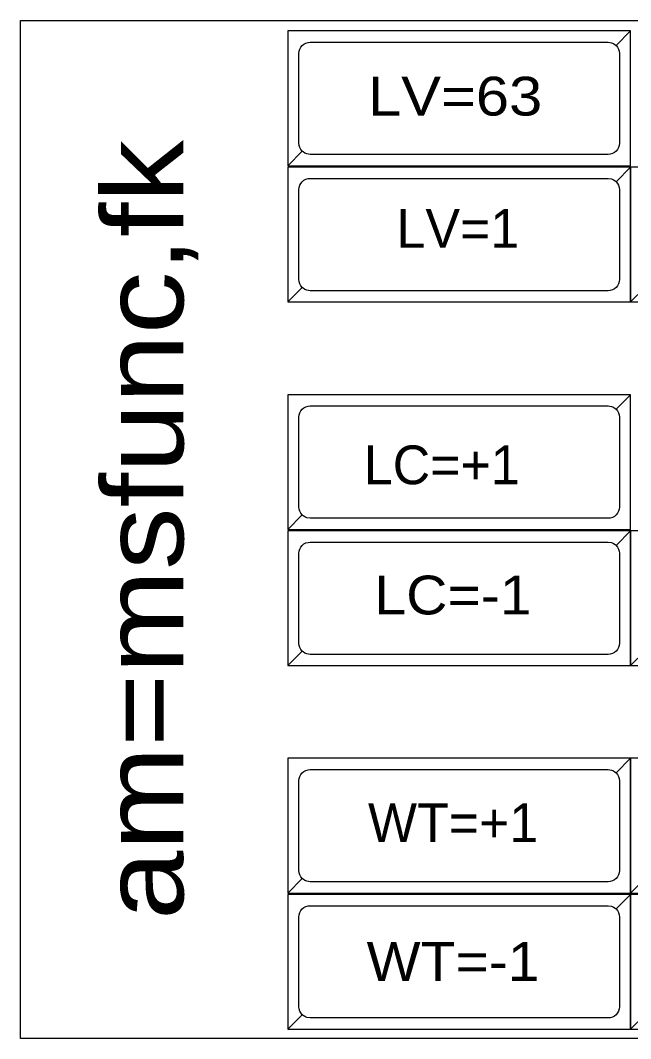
# Model space of a CAD drawing. Extents: x 16898 to 16911.6, y 15837.8 to 15842.
# Drawn here: x 16897.996 to 16899.217, y 15839.972 to 15842.012 of the extents above; entities that cross this region are included whole.
import ezdxf
from ezdxf.enums import TextEntityAlignment as Align

# ---------------------------------------------------------------- set-up
doc = ezdxf.new("R2010")
doc.units = 0
doc.header["$LTSCALE"] = 0.018
for name, color, linetype, lineweight in [('1', 7, 'Continuous', 25), ('2', 7, 'Continuous', 13), ('5', 7, 'Continuous', 13)]:
    doc.layers.add(name, color=color, linetype=linetype, lineweight=lineweight)

msp = doc.modelspace()

# ---------------------------------------------------------------- linework, layer by layer
at = {"layer": '1'}
for points in [[(16897.9955, 15839.9723), (16897.9955, 15842.0124), (16911.4764, 15842.0124), (16911.5674, 15841.9251), (16911.5674, 15840.0599), (16911.4764, 15839.9723)], [(16898.5307, 15841.7212), (16899.2171, 15841.7212), (16899.2171, 15841.9912), (16898.5307, 15841.9912)], [(16898.5307, 15841.7212), (16899.2171, 15841.7212), (16899.2171, 15841.9912), (16899.188, 15841.9621), (16899.1908, 15841.9587), (16899.1929, 15841.9548), (16899.1941, 15841.9506), (16899.1946, 15841.9462), (16899.1946, 15841.7662), (16899.1941, 15841.7618), (16899.1929, 15841.7576), (16899.1908, 15841.7537), (16899.188, 15841.7503), (16899.188, 15841.7503), (16899.1846, 15841.7475), (16899.1807, 15841.7454), (16899.1765, 15841.7441), (16899.1721, 15841.7437), (16898.5757, 15841.7437), (16898.5691, 15841.7447), (16898.5651, 15841.7464), (16898.5614, 15841.7488), (16898.5598, 15841.7503)], [(16899.2171, 15841.9912), (16898.5307, 15841.9912), (16898.5307, 15841.7212), (16898.5598, 15841.7503), (16898.557, 15841.7537), (16898.5549, 15841.7576), (16898.5536, 15841.7618), (16898.5532, 15841.7662), (16898.5532, 15841.9462), (16898.5536, 15841.9506), (16898.5549, 15841.9548), (16898.557, 15841.9587), (16898.5598, 15841.9621), (16898.5598, 15841.9621), (16898.5632, 15841.9649), (16898.5671, 15841.967), (16898.5713, 15841.9682), (16898.5757, 15841.9687), (16899.1721, 15841.9687), (16899.1787, 15841.9677), (16899.1827, 15841.966), (16899.1864, 15841.9636), (16899.188, 15841.9621)], [(16898.5307, 15841.4483), (16899.2171, 15841.4483), (16899.2171, 15841.7183), (16898.5307, 15841.7183)], [(16898.5307, 15841.4483), (16899.2171, 15841.4483), (16899.2171, 15841.7183), (16899.188, 15841.6892), (16899.1908, 15841.6858), (16899.1929, 15841.6819), (16899.1941, 15841.6777), (16899.1946, 15841.6733), (16899.1946, 15841.4933), (16899.1941, 15841.4889), (16899.1929, 15841.4847), (16899.1908, 15841.4808), (16899.188, 15841.4774), (16899.188, 15841.4774), (16899.1846, 15841.4746), (16899.1807, 15841.4725), (16899.1765, 15841.4712), (16899.1721, 15841.4708), (16898.5757, 15841.4708), (16898.5691, 15841.4718), (16898.5651, 15841.4735), (16898.5614, 15841.4759), (16898.5598, 15841.4774)], [(16899.2171, 15841.7183), (16898.5307, 15841.7183), (16898.5307, 15841.4483), (16898.5598, 15841.4774), (16898.557, 15841.4808), (16898.5549, 15841.4847), (16898.5536, 15841.4889), (16898.5532, 15841.4933), (16898.5532, 15841.6733), (16898.5536, 15841.6777), (16898.5549, 15841.6819), (16898.557, 15841.6858), (16898.5598, 15841.6892), (16898.5598, 15841.6892), (16898.5632, 15841.692), (16898.5671, 15841.6941), (16898.5713, 15841.6953), (16898.5757, 15841.6958), (16899.1721, 15841.6958), (16899.1787, 15841.6948), (16899.1827, 15841.6931), (16899.1864, 15841.6907), (16899.188, 15841.6892)], [(16899.2171, 15841.4483), (16899.9035, 15841.4483), (16899.9035, 15841.7183), (16899.2171, 15841.7183)], [(16899.2171, 15841.4483), (16899.9035, 15841.4483), (16899.9035, 15841.7183), (16899.8744, 15841.6892), (16899.8772, 15841.6858), (16899.8793, 15841.6819), (16899.8805, 15841.6777), (16899.881, 15841.6733), (16899.881, 15841.4933), (16899.8805, 15841.4889), (16899.8793, 15841.4847), (16899.8772, 15841.4808), (16899.8744, 15841.4774), (16899.8744, 15841.4774), (16899.871, 15841.4746), (16899.8671, 15841.4725), (16899.8629, 15841.4712), (16899.8585, 15841.4708), (16899.2621, 15841.4708), (16899.2555, 15841.4718), (16899.2515, 15841.4735), (16899.2478, 15841.4759), (16899.2462, 15841.4774)], [(16899.9035, 15841.7183), (16899.2171, 15841.7183), (16899.2171, 15841.4483), (16899.2462, 15841.4774), (16899.2434, 15841.4808), (16899.2413, 15841.4847), (16899.24, 15841.4889), (16899.2396, 15841.4933), (16899.2396, 15841.6733), (16899.24, 15841.6777), (16899.2413, 15841.6819), (16899.2434, 15841.6858), (16899.2462, 15841.6892), (16899.2462, 15841.6892), (16899.2496, 15841.692), (16899.2535, 15841.6941), (16899.2577, 15841.6953), (16899.2621, 15841.6958), (16899.8585, 15841.6958), (16899.8651, 15841.6948), (16899.8691, 15841.6931), (16899.8728, 15841.6907), (16899.8744, 15841.6892)], [(16898.5307, 15840.9924), (16899.2171, 15840.9924), (16899.2171, 15841.2624), (16898.5307, 15841.2624)], [(16898.5307, 15840.9924), (16899.2171, 15840.9924), (16899.2171, 15841.2624), (16899.188, 15841.2333), (16899.1908, 15841.2299), (16899.1929, 15841.226), (16899.1941, 15841.2218), (16899.1946, 15841.2174), (16899.1946, 15841.0374), (16899.1941, 15841.033), (16899.1929, 15841.0288), (16899.1908, 15841.0249), (16899.188, 15841.0215), (16899.188, 15841.0215), (16899.1846, 15841.0187), (16899.1807, 15841.0166), (16899.1765, 15841.0153), (16899.1721, 15841.0149), (16898.5757, 15841.0149), (16898.5691, 15841.0159), (16898.5651, 15841.0176), (16898.5614, 15841.02), (16898.5598, 15841.0215)], [(16899.2171, 15841.2624), (16898.5307, 15841.2624), (16898.5307, 15840.9924), (16898.5598, 15841.0215), (16898.557, 15841.0249), (16898.5549, 15841.0288), (16898.5536, 15841.033), (16898.5532, 15841.0374), (16898.5532, 15841.2174), (16898.5536, 15841.2218), (16898.5549, 15841.226), (16898.557, 15841.2299), (16898.5598, 15841.2333), (16898.5598, 15841.2333), (16898.5632, 15841.2361), (16898.5671, 15841.2382), (16898.5713, 15841.2394), (16898.5757, 15841.2399), (16899.1721, 15841.2399), (16899.1787, 15841.2389), (16899.1827, 15841.2372), (16899.1864, 15841.2348), (16899.188, 15841.2333)], [(16898.5307, 15840.7196), (16899.2171, 15840.7196), (16899.2171, 15840.9896), (16898.5307, 15840.9896)], [(16898.5307, 15840.7196), (16899.2171, 15840.7196), (16899.2171, 15840.9896), (16899.188, 15840.9605), (16899.1908, 15840.9571), (16899.1929, 15840.9532), (16899.1941, 15840.949), (16899.1946, 15840.9446), (16899.1946, 15840.7646), (16899.1941, 15840.7602), (16899.1929, 15840.756), (16899.1908, 15840.7521), (16899.188, 15840.7487), (16899.188, 15840.7487), (16899.1846, 15840.7459), (16899.1807, 15840.7438), (16899.1765, 15840.7425), (16899.1721, 15840.7421), (16898.5757, 15840.7421), (16898.5691, 15840.7431), (16898.5651, 15840.7448), (16898.5614, 15840.7472), (16898.5598, 15840.7487)], [(16899.2171, 15840.9896), (16898.5307, 15840.9896), (16898.5307, 15840.7196), (16898.5598, 15840.7487), (16898.557, 15840.7521), (16898.5549, 15840.756), (16898.5536, 15840.7602), (16898.5532, 15840.7646), (16898.5532, 15840.9446), (16898.5536, 15840.949), (16898.5549, 15840.9532), (16898.557, 15840.9571), (16898.5598, 15840.9605), (16898.5598, 15840.9605), (16898.5632, 15840.9633), (16898.5671, 15840.9654), (16898.5713, 15840.9666), (16898.5757, 15840.9671), (16899.1721, 15840.9671), (16899.1787, 15840.9661), (16899.1827, 15840.9644), (16899.1864, 15840.962), (16899.188, 15840.9605)], [(16899.2171, 15840.7196), (16899.9035, 15840.7196), (16899.9035, 15840.9896), (16899.2171, 15840.9896)], [(16899.2171, 15840.7196), (16899.9035, 15840.7196), (16899.9035, 15840.9896), (16899.8744, 15840.9605), (16899.8772, 15840.9571), (16899.8793, 15840.9532), (16899.8805, 15840.949), (16899.881, 15840.9446), (16899.881, 15840.7646), (16899.8805, 15840.7602), (16899.8793, 15840.756), (16899.8772, 15840.7521), (16899.8744, 15840.7487), (16899.8744, 15840.7487), (16899.871, 15840.7459), (16899.8671, 15840.7438), (16899.8629, 15840.7425), (16899.8585, 15840.7421), (16899.2621, 15840.7421), (16899.2555, 15840.7431), (16899.2515, 15840.7448), (16899.2478, 15840.7472), (16899.2462, 15840.7487)], [(16899.9035, 15840.9896), (16899.2171, 15840.9896), (16899.2171, 15840.7196), (16899.2462, 15840.7487), (16899.2434, 15840.7521), (16899.2413, 15840.756), (16899.24, 15840.7602), (16899.2396, 15840.7646), (16899.2396, 15840.9446), (16899.24, 15840.949), (16899.2413, 15840.9532), (16899.2434, 15840.9571), (16899.2462, 15840.9605), (16899.2462, 15840.9605), (16899.2496, 15840.9633), (16899.2535, 15840.9654), (16899.2577, 15840.9666), (16899.2621, 15840.9671), (16899.8585, 15840.9671), (16899.8651, 15840.9661), (16899.8691, 15840.9644), (16899.8728, 15840.962), (16899.8744, 15840.9605)], [(16898.5307, 15840.264), (16899.2171, 15840.264), (16899.2171, 15840.534), (16898.5307, 15840.534)], [(16898.5307, 15840.264), (16899.2171, 15840.264), (16899.2171, 15840.534), (16899.188, 15840.5049), (16899.1908, 15840.5015), (16899.1929, 15840.4976), (16899.1941, 15840.4934), (16899.1946, 15840.489), (16899.1946, 15840.309), (16899.1941, 15840.3046), (16899.1929, 15840.3004), (16899.1908, 15840.2965), (16899.188, 15840.2931), (16899.188, 15840.2931), (16899.1846, 15840.2903), (16899.1807, 15840.2882), (16899.1765, 15840.2869), (16899.1721, 15840.2865), (16898.5757, 15840.2865), (16898.5691, 15840.2875), (16898.5651, 15840.2892), (16898.5614, 15840.2916), (16898.5598, 15840.2931)], [(16899.2171, 15840.534), (16898.5307, 15840.534), (16898.5307, 15840.264), (16898.5598, 15840.2931), (16898.557, 15840.2965), (16898.5549, 15840.3004), (16898.5536, 15840.3046), (16898.5532, 15840.309), (16898.5532, 15840.489), (16898.5536, 15840.4934), (16898.5549, 15840.4976), (16898.557, 15840.5015), (16898.5598, 15840.5049), (16898.5598, 15840.5049), (16898.5632, 15840.5077), (16898.5671, 15840.5098), (16898.5713, 15840.511), (16898.5757, 15840.5115), (16899.1721, 15840.5115), (16899.1787, 15840.5105), (16899.1827, 15840.5088), (16899.1864, 15840.5064), (16899.188, 15840.5049)], [(16899.2171, 15840.264), (16899.9035, 15840.264), (16899.9035, 15840.534), (16899.2171, 15840.534)], [(16899.2171, 15840.264), (16899.9035, 15840.264), (16899.9035, 15840.534), (16899.8744, 15840.5049), (16899.8772, 15840.5015), (16899.8793, 15840.4976), (16899.8805, 15840.4934), (16899.881, 15840.489), (16899.881, 15840.309), (16899.8805, 15840.3046), (16899.8793, 15840.3004), (16899.8772, 15840.2965), (16899.8744, 15840.2931), (16899.8744, 15840.2931), (16899.871, 15840.2903), (16899.8671, 15840.2882), (16899.8629, 15840.2869), (16899.8585, 15840.2865), (16899.2621, 15840.2865), (16899.2555, 15840.2875), (16899.2515, 15840.2892), (16899.2478, 15840.2916), (16899.2462, 15840.2931)], [(16899.9035, 15840.534), (16899.2171, 15840.534), (16899.2171, 15840.264), (16899.2462, 15840.2931), (16899.2434, 15840.2965), (16899.2413, 15840.3004), (16899.24, 15840.3046), (16899.2396, 15840.309), (16899.2396, 15840.489), (16899.24, 15840.4934), (16899.2413, 15840.4976), (16899.2434, 15840.5015), (16899.2462, 15840.5049), (16899.2462, 15840.5049), (16899.2496, 15840.5077), (16899.2535, 15840.5098), (16899.2577, 15840.511), (16899.2621, 15840.5115), (16899.8585, 15840.5115), (16899.8651, 15840.5105), (16899.8691, 15840.5088), (16899.8728, 15840.5064), (16899.8744, 15840.5049)], [(16898.5307, 15839.9912), (16899.2171, 15839.9912), (16899.2171, 15840.2612), (16898.5307, 15840.2612)], [(16898.5307, 15839.9912), (16899.2171, 15839.9912), (16899.2171, 15840.2612), (16899.188, 15840.2321), (16899.1908, 15840.2287), (16899.1929, 15840.2248), (16899.1941, 15840.2206), (16899.1946, 15840.2162), (16899.1946, 15840.0362), (16899.1941, 15840.0318), (16899.1929, 15840.0276), (16899.1908, 15840.0237), (16899.188, 15840.0203), (16899.188, 15840.0203), (16899.1846, 15840.0175), (16899.1807, 15840.0154), (16899.1765, 15840.0141), (16899.1721, 15840.0137), (16898.5757, 15840.0137), (16898.5691, 15840.0147), (16898.5651, 15840.0164), (16898.5614, 15840.0188), (16898.5598, 15840.0203)], [(16899.2171, 15840.2612), (16898.5307, 15840.2612), (16898.5307, 15839.9912), (16898.5598, 15840.0203), (16898.557, 15840.0237), (16898.5549, 15840.0276), (16898.5536, 15840.0318), (16898.5532, 15840.0362), (16898.5532, 15840.2162), (16898.5536, 15840.2206), (16898.5549, 15840.2248), (16898.557, 15840.2287), (16898.5598, 15840.2321), (16898.5598, 15840.2321), (16898.5632, 15840.2349), (16898.5671, 15840.237), (16898.5713, 15840.2382), (16898.5757, 15840.2387), (16899.1721, 15840.2387), (16899.1787, 15840.2377), (16899.1827, 15840.236), (16899.1864, 15840.2336), (16899.188, 15840.2321)], [(16899.2171, 15839.9912), (16899.9035, 15839.9912), (16899.9035, 15840.2612), (16899.2171, 15840.2612)], [(16899.2171, 15839.9912), (16899.9035, 15839.9912), (16899.9035, 15840.2612), (16899.8744, 15840.2321), (16899.8772, 15840.2287), (16899.8793, 15840.2248), (16899.8805, 15840.2206), (16899.881, 15840.2162), (16899.881, 15840.0362), (16899.8805, 15840.0318), (16899.8793, 15840.0276), (16899.8772, 15840.0237), (16899.8744, 15840.0203), (16899.8744, 15840.0203), (16899.871, 15840.0175), (16899.8671, 15840.0154), (16899.8629, 15840.0141), (16899.8585, 15840.0137), (16899.2621, 15840.0137), (16899.2555, 15840.0147), (16899.2515, 15840.0164), (16899.2478, 15840.0188), (16899.2462, 15840.0203)], [(16899.9035, 15840.2612), (16899.2171, 15840.2612), (16899.2171, 15839.9912), (16899.2462, 15840.0203), (16899.2434, 15840.0237), (16899.2413, 15840.0276), (16899.24, 15840.0318), (16899.2396, 15840.0362), (16899.2396, 15840.2162), (16899.24, 15840.2206), (16899.2413, 15840.2248), (16899.2434, 15840.2287), (16899.2462, 15840.2321), (16899.2462, 15840.2321), (16899.2496, 15840.2349), (16899.2535, 15840.237), (16899.2577, 15840.2382), (16899.2621, 15840.2387), (16899.8585, 15840.2387), (16899.8651, 15840.2377), (16899.8691, 15840.236), (16899.8728, 15840.2336), (16899.8744, 15840.2321)]]:
    msp.add_lwpolyline(points, close=True, dxfattribs=at)
at = {"layer": '2'}
msp.add_lwpolyline([(16897.9955, 15839.9723), (16897.9955, 15842.0124), (16911.4764, 15842.0124), (16911.5674, 15841.9251), (16911.5674, 15840.0599), (16911.4764, 15839.9723)], close=True, dxfattribs=at)

# ---------------------------------------------------------------- texts
at = {"layer": '1', "width": 1.15}
msp.add_text('am=msfunc,fk', height=0.1625, rotation=90, dxfattribs=at).set_placement((16898.3218, 15840.9914), align=Align.CENTER)
at = {"layer": '5'}
for s, width, p in [('LV=63', 1.15, (16898.8658, 15841.8217)), ('LC=-1', 1.1, (16898.8616, 15840.8222)), ('WT=-1', 1.1, (16898.8618, 15840.0879))]:
    msp.add_text(s, height=0.07772, dxfattribs=dict(at, width=width)).set_placement(p, align=Align.CENTER)
for s, p in [('LV=1', (16898.8714, 15841.5567)), ('LC=+1', (16898.8391, 15841.083)), ('WT=+1', (16898.8618, 15840.366))]:
    msp.add_text(s, height=0.07772, dxfattribs=at).set_placement(p, align=Align.CENTER)

doc.saveas('drawing.dxf')
